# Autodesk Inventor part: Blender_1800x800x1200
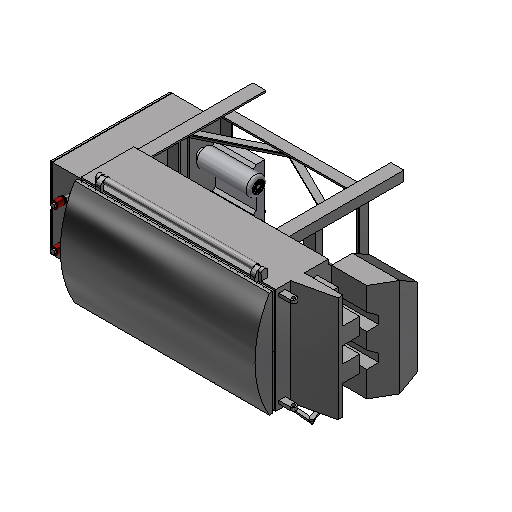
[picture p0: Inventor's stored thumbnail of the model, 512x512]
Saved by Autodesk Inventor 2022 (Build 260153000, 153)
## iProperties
Created: 2014-02
Part Number: Blender_1800x800x1200
Material: 一般
Document SubType Name: Modeling
Density: 1 g/cm^3
Appearance: 既定
Key Parameters: Width=1800.000 mm;Depth=800.000 mm;Height=1200.000 mm;
Author: Autodest, Inc.
Title: Blender
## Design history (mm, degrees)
sketch "Sketch1"
  geometry: L1 (0, -407.63)-(0, 422.253); L2 (-798, 0)-(798, 0); L3 (-473.684, 331)-(-391.866, 331); L4 (-391.866, 331)-(-391.866, 321); L5 (-463.684, 269.462)-(-473.684, 269.462); L6 (-473.684, 269.462)-(-473.684, 331); L7 (-463.684, 269.462)-(-463.684, 321); L8 (-463.684, 321)-(-391.866, 321); L9 (-473.684, -331)-(-391.866, -331); L10 (-391.866, -331)-(-391.866, -321); L11 (-463.684, -269.462)-(-473.684, -269.462); L12 (-473.684, -269.462)-(-473.684, -331); L13 (-463.684, -269.462)-(-463.684, -321); L14 (-463.684, -321)-(-391.866, -321); L15 (463.684, -269.462)-(473.684, -269.462); L16 (463.684, -321)-(391.866, -321); L17 (473.684, -331)-(391.866, -331); L18 (391.866, -331)-(391.866, -321); L19 (473.684, -269.462)-(473.684, -331); L20 (463.684, -269.462)-(463.684, -321); L21 (463.684, 269.462)-(463.684, 321); L22 (473.684, 269.462)-(473.684, 331); L23 (463.684, 321)-(391.866, 321); L24 (391.866, 331)-(391.866, 321); L25 (473.684, 331)-(391.866, 331); L26 (463.684, 269.462)-(473.684, 269.462); L27 (0, 588.23)-(0, -573.606) reference; L28 (-1117.2, 0)-(1117.2, 0) reference; 1 further point
  constraints: 52 end point, 18 symmetric about line, 3 parallel, 3 perpendicular, 2 collinear, 1 horizontal
  dimensions: "d0" = 81.81818 distance of L3.start L3.end (derived); "d1" = 61.53846 distance of L5.end L3.start (derived); "d2" = 10 distance of L3.end L4.end; "d3" = 331 distance between parallel lines of L2 L3 (derived); "d4" = 473.68421 distance between parallel lines of L1 L6 (derived)
extrude "Extrusion1" new body sketch "Sketch1" distance "d5" = 720 (derived); taper "d6" = 0 deg
sketch "Sketch2"
  geometry: L1 (0, 51.538)-(-720, 51.538) reference; L2 (0, 0)-(-720, 0) reference; L3 (0, 642)-(-720, 642) reference; L4 (-266.667, 0)-(-200, 0); L5 (-200, 51.538)-(-200, 0); L6 (-200, 642)-(-200, 590.462); L7 (-200, 642)-(-266.667, 642); L8 (-266.667, 0)-(-266.667, 642); L9 (-266.667, 0)-(-266.667, 10.308); L10 (-266.667, 0)-(-266.667, 10.308); L11 (-266.667, 10.308)-(-210.308, 10.308); L12 (-210.308, 10.308)-(-210.308, 51.538); L13 (-200, 51.538)-(-210.308, 51.538); L14 (-266.667, 642)-(-266.667, 631.692); L15 (-266.667, 631.692)-(-210.308, 631.692); L16 (-210.308, 631.692)-(-210.308, 590.462); L17 (-210.308, 590.462)-(-200, 590.462); L18 (0, 0)-(0, 51.538) reference; 1 further point
  constraints: 28 end point, 8 point on line, 6 perpendicular, 4 equal length, 3 collinear, 1 parallel, 1 vertical
  dimensions: "d9" = 66.66667 distance between parallel lines of L5 L8 (derived); "d10" = 200 distance between parallel lines of L18 L5 (= 3 x d9); "d11" = 51.53846 distance of L2.start L1.start (derived); "d12" = 10.30769 distance between parallel lines of L11 L4 (= 0.2 x d11)
extrude "Extrusion2" join sketch "Sketch2" stored distance "d7" = 720 (derived); taper "d8" = 0 deg
sketch "Sketch3"
  geometry: L1 (0, -56.359)-(927.368, -56.359) reference; L2 (463.684, 601.778)-(463.684, -437.333) reference; L3 (927.368, 0)-(927.368, 453.333) reference; L4 (463.684, -56.359)-(927.368, 170.308); L5 (927.368, 170.308)-(909.261, 207.35); L6 (909.261, 207.35)-(445.577, -19.317); L7 (445.577, -19.317)-(463.684, -56.359); 1 further point
  constraints: 8 end point, 2 parallel, 2 point on line, 1 midpoint, 1 perpendicular
  dimensions: "d13" = 226.66667 distance of L1.end L4.end (= 0.5 x d14); "d14" = 453.33333 distance of L3.start L3.end (derived); "d17" = 41.23077 distance between parallel lines of L4 L6 (= 0.8 x d11)
extrude "Extrusion3" join sketch "Sketch3" distance "d15" = 6.18462 (= 0.6 x d12); taper "d16" = 0 deg
sketch "Sketch4"
  geometry: L1 (463.684, -56.359)-(927.368, 170.308) reference; L2 (463.684, -56.359)-(927.368, 170.308); L3 (927.368, 170.308)-(922.842, 179.568); L4 (922.842, 179.568)-(459.157, -47.099); L5 (459.157, -47.099)-(463.684, -56.359); 1 further point
  constraints: 8 end point, 3 equal length, 1 perpendicular
  dimensions: "d18" = 10.30769 distance between parallel lines of L2 L4 (= d12)
extrude "Extrusion4" join sketch "Sketch4" stored distance "d19" = 5; taper "d20" = 0 deg
mirror "Mirror1"
mirror "Mirror2"
sketch "Sketch5"
  geometry: L1 (0, 1560)-(0, -260) reference; L2 (-463.4, 0)-(463.4, 0) reference; L3 (331, 0)-(331, 720) reference; L4 (-331, 0)-(-331, 720) reference; L5 (-331, 1200)-(-331, 720); L6 (331, 1200)-(331, 720); L7 (-331, 545.455)-(331, 545.455); L8 (-331, 720)-(-300.231, 720); L9 (331, 720)-(300.231, 720); L10 (-300.231, 720)-(-300.231, 1218.082); L11 (300.231, 720)-(300.231, 1223.148); L12 (-331, 1050)-(-331, 720); L13 (-331, 1200)-(331, 1200); L14 (-331, 1050)-(331, 1050); L15 (331, 1050)-(331, 720); L16 (-269.462, 436.974)-(-269.462, 720) reference; A1 r 345.482 centre (0, 890.937) between (-300.231, 720) and (300.231, 720); 1 further point
  constraints: 23 end point, 6 collinear, 6 point on line, 3 parallel, 3 perpendicular, 2 point on circle, 1 centre point, 1 tangent
  dimensions: "d23" = 1200 distance between parallel lines of L2 L13 (derived); "d24" = 150 distance from line of L13 L12.start (derived); "d123" = 545.45455 distance between parallel lines of L2 L7 (derived); "d124" = 61.53846 distance of L16.end L4.end (derived); "d125" = 30.76923 distance of L4.end L8.end (derived)
extrude "Extrusion5" new body sketch "Sketch5" distance "d25" = 720 (derived); taper "d27" = 0 deg; dims "d26" = 500 (derived), "d28" = 0
shell "Shell1" dims "d29" = 10
sketch "Sketch6"
  geometry: L1 (1220, 0)-(0, 0) reference; L2 (1220, 330)-(1220, 0) reference; L3 (0, 0)-(0, 330) reference; L4 (1130, 0)-(1110, 0); L5 (1110, 0)-(1110, 40); L6 (1110, 40)-(1130, 40); L7 (1130, 40)-(1130, 0); L8 (110, 0)-(90, 0); L9 (90, 0)-(90, 40); L10 (90, 40)-(110, 40); L11 (110, 40)-(110, 0); 1 further point
  constraints: 16 end point, 4 parallel, 2 collinear, 2 horizontal, 2 perpendicular, 2 point on line
  dimensions: "d30" = 90 distance between parallel lines of L2 L7 (derived); "d31" = 90 distance between parallel lines of L3 L9 (= d30); "d32" = 40 distance of L4.end L5.end; "d33" = 20 distance of L5.end L6.end
extrude "Extrusion6" join sketch "Sketch6" distance "d34" = 60; taper "d35" = 0 deg
sketch "Sketch7"
  geometry: L1 (40, 0)-(0, 0) reference; L2 (40, 0)-(40, 60) reference; L3 (0, 60)-(40, 60) reference; L4 (0, 0)-(0, 60) reference; L5 (0, 40)-(40, 40); A1 r 20 centre (20, 40) between (40, 40) and (0, 40); 1 further point
  constraints: 2 end point, 2 point on circle, 2 point on line, 1 centre point, 1 perpendicular, 1 tangent
  dimensions: "d36" = 40 distance of L3.start L2.end (derived); "d37" = 20 distance between parallel lines of L3 L5 (= 0.5 x d36)
extrude "Extrusion7" cut sketch "Sketch7" stored distance "d38" = 50; taper "d39" = 0 deg
workplane "Work Plane1"
  workaxis "Work Axis1"
sketch "Sketch8"
  geometry: L1 (-558.164, 1030)-(1022.249, 1030) reference; L2 (-321, 1050)-(321, 1050); L3 (321, 1050)-(321, 1070); L4 (321, 1070)-(331, 1070); L5 (-321, 1050)-(-321, 1070); L6 (-321, 1070)-(-331, 1070); L7 (-331, 1070)-(-331, 1090); L8 (331, 1070)-(331, 1090); L9 (-332.391, 1180)-(796.476, 1180); L10 (-321, 730)-(-321, 1050) reference; L11 (321, 1050)-(321, 730) reference; A1 r 653.672 centre (0, 526.328) between (331, 1090) and (-331, 1090); A2 r 20 centre (371, 1030) between (371, 1010) and (371, 1050) reference; 1 further point
  constraints: 16 end point, 4 parallel, 4 perpendicular, 2 equal length, 2 point on circle, 1 centre point, 1 collinear, 1 tangent
  dimensions: "d45" = 150 distance between parallel lines of L1 L9 (derived); "d46" = 20 distance between parallel lines of L1 L2; "d47" = 642 distance of L11.start L10.end (derived); "d48" = 642 distance of L2.start L2.end (= d47); "d50" = 20 distance between parallel lines of L2 L6; "d55" = 10 distance of L3.end L4.end; "d56" = 20 distance of L6.end L7.end; "d57" = 50 distance from line of L11 A2.centre (derived); "d58" = 50 distance from line of A2.centre L3 (= d57)
extrude "Extrusion8" new body sketch "Sketch8" distance "d41" = 720 (= d25); taper "d43" = 0 deg; dims "d42" = 500 (= d26), "d44" = 0
sketch "Sketch10"
  geometry: L1 (0, 0)-(1220, 0) reference; L2 (1220, 642)-(1220, 0) reference; L3 (1220, 642)-(0, 642) reference; L4 (0, 0)-(0, 642) reference; L5 (1210, 642)-(1210, 0); L6 (10, 642)-(10, 0); 1 further point
  constraints: 4 end point, 4 point on line, 2 perpendicular
  dimensions: "d64" = 10 distance between parallel lines of L2 L5; "d65" = 10 distance between parallel lines of L4 L6
extrude "Extrusion10" cut sketch "Sketch10" stored distance "d66" = 762.5; taper "d67" = 0 deg
shell "Shell3" dims "d68" = 5
sketch "Sketch11"
  geometry: L1 (-20, 0)-(-20, -662) reference; L2 (0, -10)-(-20, -10) reference; L3 (0, -652)-(0, -10) reference; L4 (0, -10)-(0, 18); L5 (-20, 0)-(-20, 18); L6 (-20, 18)-(0, 18); A1 r 20 centre (20, 40) between (40, 40) and (0, 40) reference; A2 r 17 centre (20, 40) between (11.881, 25.064) and (20.755, 56.983); A3 r 8.041 centre (8.041, 18) between (11.881, 25.064) and (0, 18); A4 r 39.022 centre (19.022, 18) between (20.755, 56.983) and (-20, 18); 1 further point
  constraints: 6 end point, 6 point on circle, 4 tangent, 3 centre point, 1 coincident, 1 collinear, 1 parallel, 1 perpendicular
  dimensions: "d69" = 3 radial gap between concentric circles of A1 A2; "d72" = 28 distance of L2.start L4.end
extrude "Extrusion11" join sketch "Sketch11" distance "d70" = 30; taper "d71" = 0 deg
sketch "Sketch12"
  geometry: L1 (60, -662)-(60, 0) reference; L2 (60, -10)-(40, -10) reference; L3 (40, -10)-(40, -652) reference; L4 (60, 0)-(60, 18); L5 (60, 18)-(40, 18); L6 (40, 18)-(40, -10); A1 r 20 centre (20, 40) between (40, 40) and (0, 40) reference; A2 r 17 centre (20, 40) between (28.119, 25.064) and (19.245, 56.983); A3 r 8.041 centre (31.959, 18) between (40, 18) and (28.119, 25.064); A4 r 39.022 centre (20.978, 18) between (60, 18) and (19.245, 56.983); 1 further point
  constraints: 6 end point, 6 point on circle, 4 tangent, 3 centre point, 2 parallel, 1 coincident, 1 collinear, 1 perpendicular
  dimensions: "d73" = 3 radial gap between concentric circles of A1 A2; "d74" = 28 distance of L5.end L2.end
extrude "Extrusion12" join sketch "Sketch12" distance "d75" = 30; taper "d76" = 0 deg
sketch "Sketch13"
  geometry: C1 r 20 at (20, 40); A1 r 20 centre (20, 40) between (40, 40) and (0, 40) reference; 2 further points
  constraints: 1 centre point, 1 coincident, 1 concentric
extrude "Extrusion13" join sketch "Sketch13" stored distance "d77" = 30; taper "d78" = 0 deg
sketch "Sketch14"
  geometry: L1 (71.818, -453.333)-(71.818, 0) reference; L2 (0, -453.333)-(0, 0) reference; L3 (-783.732, -720)-(-783.732, 0) reference; L4 (-891.866, 0)-(328.134, 0) reference; L5 (-865.55, -720)-(-865.55, 0) reference; L6 (0, -174.545)-(71.818, -174.545); L7 (71.818, -174.545)-(71.818, -184.545); L8 (71.818, -184.545)-(0, -184.545); L9 (0, -184.545)-(0, -174.545); L10 (71.818, -184.545)-(61.818, -184.545); L11 (61.818, -184.545)-(61.818, -220.455); L12 (61.818, -220.455)-(71.818, -220.455); L13 (71.818, -220.455)-(71.818, -184.545); L14 (-783.732, -174.545)-(-855.55, -174.545); L15 (-855.55, -174.545)-(-855.55, -184.545); L16 (-855.55, -184.545)-(-783.732, -184.545); L17 (-783.732, -184.545)-(-783.732, -174.545); L18 (-855.55, -184.545)-(-845.55, -184.545); L19 (-845.55, -184.545)-(-845.55, -220.455); L20 (-845.55, -220.455)-(-855.55, -220.455); L21 (-855.55, -220.455)-(-855.55, -184.545); L22 (-891.866, -174.545)-(328.134, -174.545) reference; 1 further point
  constraints: 32 end point, 7 parallel, 5 collinear, 4 horizontal, 4 perpendicular, 3 point on line, 2 equal length
  dimensions: "d79" = 10 distance of L8.end L6.start; "d82" = 10 distance of L11.end L12.end (derived); "d83" = 35.90909 distance between parallel lines of L12 L10 (derived); "d84" = 71.81818 distance of L7.end L8.end (derived)
extrude "Extrusion14" join sketch "Sketch14" stored distance "d80" = 30; taper "d81" = 0 deg
sketch "Sketch15"
  geometry: L1 (0, 0)-(0, 56.359) reference; L2 (0, 0)-(927.368, 0) reference; L3 (71.818, -10.308)-(855.55, -10.308) reference; L4 (927.368, 56.359)-(927.368, 289.238) reference; L5 (0, 56.359)-(8, 56.359); L6 (8, 56.359)-(8, 0); L7 (8, 0)-(0, 0); L8 (0, 0)-(0, 56.359); L9 (8, 0)-(71.818, 0); L10 (71.818, 0)-(71.818, 8); L11 (71.818, 8)-(8, 8); L12 (8, 8)-(8, 0); L13 (71.818, 56.359)-(71.818, 325.147) reference; L14 (855.55, 56.359)-(855.55, 325.147) reference; L15 (855.55, 56.359)-(927.368, 56.359) reference; L16 (927.368, 56.359)-(919.368, 56.359); L17 (919.368, 56.359)-(919.368, 0); L18 (919.368, 0)-(927.368, 0); L19 (927.368, 0)-(927.368, 56.359); L20 (927.368, 0)-(855.55, 0); L21 (855.55, 0)-(855.55, 8); L22 (855.55, 8)-(927.368, 8); L23 (927.368, 8)-(927.368, 0); 2 further points
  constraints: 32 end point, 8 parallel, 5 perpendicular, 4 collinear, 4 horizontal, 1 point on line
  dimensions: "d85" = 8 distance of L9.end L10.end; "d86" = 8 distance between parallel lines of L1 L6
extrude "Extrusion15" join sketch "Sketch15" stored distance "d88" = 30; taper "d89" = 0 deg
sketch "Sketch16"
  geometry: L1 (-56.359, 0)-(0, 0) reference; L2 (-56.359, 538.923)-(0, 538.923) reference; L3 (-56.359, 538.923)-(-56.359, 0) reference; L4 (-56.359, 157.186)-(-37.573, 157.186); L5 (-37.573, 157.186)-(-37.573, 89.821); L6 (-37.573, 89.821)-(-56.359, 89.821); L7 (-56.359, 89.821)-(-56.359, 157.186); L8 (-56.359, 381.737)-(-37.573, 381.737); L9 (-37.573, 381.737)-(-37.573, 449.103); L10 (-37.573, 449.103)-(-56.359, 449.103); L11 (-56.359, 449.103)-(-56.359, 381.737); 1 further point
  constraints: 16 end point, 4 parallel, 2 equal length, 2 horizontal, 2 perpendicular, 2 point on line
  dimensions: "d90" = 538.92308 distance of L2.start L1.start (derived); "d91" = 89.82051 distance between parallel lines of L2 L10 (derived); "d92" = 89.82051 distance between parallel lines of L1 L6 (derived); "d93" = 67.36538 distance of L8.end L9.end (derived); "d94" = 56.35897 distance of L2.start L2.end (derived); "d95" = 18.78632 distance of L9.end L10.end (derived)
extrude "Extrusion16" join sketch "Sketch16" distance "d96" = 300 (derived); taper "d97" = 0 deg
sketch "Sketch17"
  geometry: L1 (-300, 0)-(-300, 67.365) reference; L2 (-36.316, -443.276)-(-36.316, 218.724) reference; L3 (-300, 138.724)-(-51.316, 138.724); L4 (-51.316, 138.724)-(-51.316, -363.276); L5 (-51.316, -363.276)-(-300, -363.276); L6 (1183.684, -443.276)-(-36.316, -443.276) reference; L7 (-300, -102.236)-(-290, -102.236); L8 (-290, -102.236)-(-290, -122.316); L9 (-290, -122.316)-(-300, -122.316); L10 (-300, -363.276)-(-300, -122.316); L11 (-300, -102.236)-(-300, 138.724); L12 (-596.737, -112.276)-(1480.421, -112.276) reference; L13 (-290, -363.276)-(-287, -363.276); L14 (-287, -363.276)-(-287, -358.276); L15 (-287, -358.276)-(-290, -358.276); L16 (-290, -358.276)-(-290, -363.276); L17 (-290, 138.724)-(-287, 138.724); L18 (-287, 138.724)-(-287, 133.724); L19 (-287, 133.724)-(-290, 133.724); L20 (-290, 133.724)-(-290, 138.724); L21 (-10, 218.724)-(71.818, 218.724) reference; 1 further point
  constraints: 32 end point, 8 parallel, 6 collinear, 4 horizontal, 4 perpendicular, 2 point on line, 2 other
  dimensions: "d99" = 15 distance between parallel lines of L2 L4; "d100" = 80 distance between parallel lines of L6 L5; "d101" = 502 distance of L5.end L3.start (derived); "d102" = 20.08 distance of L7.end L8.end (derived); "d103" = 10 distance of L8.end L9.end; "d111" = 248.68421 distance of L3.start L3.end (derived); "d227" = 3 distance of L14.end L15.end; "d228" = 5 distance of L13.end L14.end
extrude "Extrusion17" join sketch "Sketch17" distance "d105" = 750 (derived); taper "d106" = 0 deg
sketch "Sketch18"
  geometry: L1 (-740, 720)-(-740, 480); L2 (-740, 480)-(-1036.316, 480); L3 (-1036.316, 480)-(-1036.316, 589.091); L4 (-1036.316, 589.091)-(-960.735, 720); L5 (-960.735, 720)-(-740, 720); L6 (-720, 720)-(-720, 545.455) reference; L7 (-391.866, 0)-(-463.684, 0) reference; L8 (-720, 720)-(500, 720) reference; 1 further point
  constraints: 10 end point, 2 parallel, 2 perpendicular, 1 collinear
  dimensions: "d107" = 20 distance between parallel lines of L6 L1; "d108" = 296.31579 distance of L1.end L2.end (derived); "d112" = 240 distance between parallel lines of L2 L5 (derived); "d113" = 150 deg angle of L3 L4; "d114" = 109.09091 distance of L2.end L3.end (derived)
extrude "Extrusion18" join sketch "Sketch18" stored distance "d109" = 615.38462 (derived); taper "d110" = 0 deg
sketch "Sketch19"
  geometry: L1 (0, 615.385)-(0, 0) reference; L2 (-109.091, 615.385)-(0, 615.385) reference; L3 (0, 0)-(-109.091, 0) reference; L4 (-109.091, 0)-(0, 62.984); L5 (-109.091, 615.385)-(0, 552.401); L6 (-240, 615.385)-(-240, 0) reference; L7 (-240, 160)-(-192, 187.713); L8 (-192, 187.713)-(-192, 237.713); L9 (-192, 237.713)-(-240, 265.426); L10 (-240, 365.426)-(-192, 393.138); L11 (-192, 393.138)-(-192, 443.138); L12 (-192, 443.138)-(-240, 470.851); 1 further point
  constraints: 16 end point, 6 point on line, 5 parallel, 2 collinear, 2 equal length
  dimensions: "d115" = 60 deg angle of L1 L4; "d118" = 50 distance of L7.end L8.end (derived); "d119" = 100 distance of L10.start L9.end (derived); "d120" = 48 distance between parallel lines of L6 L8 (derived); "d121" = 160 distance of L6.end L7.start (derived)
extrude "Extrusion19" cut sketch "Sketch19" stored distance "d116" = 735.5; taper "d117" = 0 deg
sketch "Sketch20"
  geometry: L1 (-720, 331)-(-1050, 331) reference; L2 (-1050, 331)-(-1050, -331) reference; L3 (-1050, -331)-(-720, -331) reference; L4 (-900, -331)-(-870, -331); L5 (-870, -331)-(-870, 331); L6 (-870, 331)-(-900, 331); L7 (-900, 331)-(-900, -331); L8 (-870, -147.692)-(-764.574, -147.692); L9 (-764.574, -147.692)-(-764.574, -42.267); L10 (-764.574, -42.267)-(-870, -42.267); L11 (-870, -42.267)-(-870, -147.692); L12 (-870, 57.733)-(-764.574, 57.733); L13 (-764.574, 57.733)-(-764.574, 163.159); L14 (-764.574, 163.159)-(-870, 163.159); L15 (-870, 163.159)-(-870, 57.733); 4 further points
  constraints: 24 end point, 6 parallel, 5 point on line, 3 equal length, 3 horizontal, 3 perpendicular, 2 collinear
  dimensions: "d126" = 30 distance between parallel lines of L5 L7; "d127" = 330 distance of L2.end L3.end (derived); "d128" = 150 distance between parallel lines of L2 L7 (derived)
extrude "Extrusion20" join sketch "Sketch20" stored distance "d129" = 735.5; taper "d130" = 0 deg
sketch "Sketch21"
  geometry: L1 (-870, -147.692)-(-870, -331) reference; L2 (-870, -331)-(-720, -331) reference; L3 (-720, -331)-(-720, -300.231) reference; L4 (-870, 331)-(-870, 163.159) reference; L5 (-870, 57.733)-(-870, -42.267) reference; L6 (-870, -42.267)-(-764.574, -42.267) reference; L7 (-870, -247.678)-(-788.182, -247.678); L8 (-788.182, -247.678)-(-788.182, -217.678); L9 (-788.182, -217.678)-(-870, -217.678); L10 (-870, -217.678)-(-870, -247.678); L11 (-870, 3.188)-(-788.182, 3.188); L12 (-788.182, 3.188)-(-788.182, 33.188); L13 (-788.182, 33.188)-(-870, 33.188); L14 (-870, 33.188)-(-870, 3.188); L15 (-870, 247.079)-(-788.182, 247.079); L16 (-788.182, 247.079)-(-788.182, 277.079); L17 (-788.182, 277.079)-(-870, 277.079); L18 (-870, 277.079)-(-870, 247.079); 1 further point
  constraints: 24 end point, 6 parallel, 4 collinear, 3 horizontal, 3 perpendicular, 2 point on line, 1 midpoint
  dimensions: "d131" = 30 distance of L7.end L8.end; "d132" = 68.18182 distance between parallel lines of L3 L8 (derived); "d133" = 150 distance of L1.end L2.end (derived); "d134" = 183.30769 distance of L1.start L1.end (derived); "d135" = 83.32168 distance between parallel lines of L2 L7 (derived); "d136" = 100 distance of L5.start L5.end (derived); "d137" = 45.45455 distance between parallel lines of L6 L11 (derived)
extrude "Extrusion21" join sketch "Sketch21" distance "d138" = 128.57143 (derived); taper "d139" = 0 deg
sketch "Sketch22"
  geometry: L1 (0, 81.818)-(128.571, 0); C1 r 12.5 at (64.286, 40.909); 2 further points
  constraints: 2 end point, 1 centre point, 1 coincident, 1 midpoint
  dimensions: "d141" = 25 diameter of C1
extrude "Extrusion22" join sketch "Sketch22" stored distance "d142" = 756.5; taper "d143" = 0 deg
sketch "Sketch23"
  geometry: C1 r 12.5 at (0, 0) reference; C2 r 9.5 at (0, 0); 1 further point
  constraints: 1 centre point, 1 coincident
  dimensions: "d144" = 3 radial gap between concentric circles of C1 C2
extrude "Extrusion23" join sketch "Sketch23" distance "d145" = 50; taper "d146" = 0 deg
sketch "Sketch24"
  geometry: L1 (0, 0)-(34.202, 93.969); L2 (-11.746, 4.275)-(22.456, 98.245); L3 (45.948, 89.694)-(11.746, -4.275); L4 (-64.286, 70.909)-(176.45, 70.909) reference; C1 r 9.5 at (0, 0) reference; C2 r 12.5 at (0, 0) reference; A1 r 12.5 centre (0, 0) between (-11.746, 4.275) and (11.746, -4.275); A2 r 12.5 centre (34.202, 93.969) between (45.948, 89.694) and (22.456, 98.245); 3 further points
  constraints: 8 end point, 4 point on circle, 4 tangent, 2 centre point, 1 coincident, 1 concentric, 1 midpoint, 1 parallel
  dimensions: "d150" = 70 deg angle of L4 L3; "d151" = 100 distance of point (0, 0) L1.end
extrude "Extrusion24" join sketch "Sketch24" distance "d148" = 10; taper "d149" = 0 deg
sketch "Sketch25"
  geometry: L1 (22.456, 98.245)-(-11.746, 4.275) reference; L2 (34.202, 93.969)-(-115.227, 80.896); L3 (35.204, 82.513)-(-114.225, 69.44); L4 (-116.229, 92.352)-(33.2, 105.426); A1 r 12.5 centre (34.202, 93.969) between (45.948, 89.694) and (22.456, 98.245) reference; A2 r 11.5 centre (34.202, 93.969) between (35.204, 82.513) and (33.2, 105.426); A3 r 11.5 centre (-115.227, 80.896) between (-116.229, 92.352) and (-114.225, 69.44); 2 further points
  constraints: 8 end point, 4 point on circle, 4 tangent, 2 centre point, 1 midpoint, 1 parallel
  dimensions: "d152" = 1 radial gap between concentric circles of A1 A2; "d153" = 65 deg angle of L1 L3; "d154" = 150 distance of L2.start L2.end
extrude "Extrusion25" join sketch "Sketch25" distance "d155" = 10; taper "d156" = 0 deg
sketch "Sketch26"
  geometry: L1 (16.122, -80.844)-(-114.225, -69.44) reference; L2 (-115.227, -80.896)-(-170.168, 36.924); L3 (-102.992, -75.191)-(-157.932, 42.629); L4 (-182.403, 31.219)-(-127.462, -86.601); A1 r 11.5 centre (-115.227, -80.896) between (-114.225, -69.44) and (-116.229, -92.352) reference; A2 r 13.5 centre (-115.227, -80.896) between (-127.462, -86.601) and (-102.992, -75.191); A3 r 13.5 centre (-170.168, 36.924) between (-157.932, 42.629) and (-182.403, 31.219); 2 further points
  constraints: 8 end point, 4 point on circle, 4 tangent, 2 centre point, 1 midpoint, 1 parallel
  dimensions: "d157" = 2 radial gap between concentric circles of A2 A1; "d158" = 130 distance of L2.start L2.end; "d159" = 120 deg angle of L3 L1
extrude "Extrusion26" join sketch "Sketch26" distance "d160" = 10; taper "d161" = 0 deg
sketch "Sketch27"
  geometry: L1 (-183.668, 50.424)-(-157.932, 50.424); L2 (-157.932, 50.424)-(-157.932, 24.689); L3 (-157.932, 24.689)-(-183.668, 24.689); L4 (-183.668, 24.689)-(-183.668, 50.424); A1 r 13.5 centre (-170.168, 36.924) between (-157.932, 42.629) and (-182.403, 31.219) reference; 1 further point
  constraints: 8 end point, 2 parallel, 2 perpendicular, 2 tangent, 1 horizontal, 1 point on line
extrude "Extrusion27" join sketch "Sketch27" stored distance "d162" = 10; taper "d163" = 0 deg
sketch "Sketch28"
  geometry: L1 (-110.405, 87.279)-(-107.288, 79.911); L2 (-107.288, 79.911)-(-112.111, 73.528); L3 (-112.111, 73.528)-(-120.05, 74.513); L4 (-120.05, 74.513)-(-123.166, 81.881); L5 (-123.166, 81.881)-(-118.344, 88.264); L6 (-118.344, 88.264)-(-110.405, 87.279); L7 (27.431, 98.23)-(34.507, 101.963); L8 (34.507, 101.963)-(41.278, 97.702); L9 (41.278, 97.702)-(40.973, 89.708); L10 (40.973, 89.708)-(33.897, 85.975); L11 (33.897, 85.975)-(27.126, 90.236); L12 (27.126, 90.236)-(27.431, 98.23); A1 r 11.5 centre (34.202, 93.969) between (35.204, 82.513) and (33.2, 105.426) reference; A2 r 11.5 centre (-115.227, 80.896) between (-116.229, 92.352) and (-114.225, 69.44) reference; 3 further points
  constraints: 24 end point, 2 coincident, 1 equal length, 26 other
  dimensions: "d164" = 8 distance of L7.end L8.end
extrude "Extrusion28" join sketch "Sketch28" distance "d165" = 8; taper "d166" = 0 deg
sketch "Sketch29"
  geometry: L1 (600, 185)-(675, 185); L2 (675, 185)-(675, 110); L3 (675, 110)-(600, 110); L4 (600, 110)-(600, 185); L5 (1220, 0)-(0, 0) reference; L6 (0, 0)-(0, 330) reference; 1 further point
  constraints: 8 end point, 2 parallel, 2 perpendicular, 1 horizontal
  dimensions: "d179" = 330 distance of L5.end L6.end (derived); "d180" = 110 distance between parallel lines of L5 L3 (derived); "d181" = 600 distance between parallel lines of L6 L4 (derived); "d182" = 75 distance of L1.end L2.end
extrude "Extrusion29" join sketch "Sketch29" distance "d167" = 8; taper "d168" = 0 deg
sketch "Sketch30"
  geometry: L1 (-179.358, 24.689)-(-127.462, -86.601) reference; L2 (-115.227, -80.896)-(-180.759, -126.782); L3 (-122.97, -69.837)-(-188.503, -115.723); L4 (-173.016, -137.841)-(-107.484, -91.954); A1 r 13.5 centre (-115.227, -80.896) between (-127.462, -86.601) and (-102.992, -75.191) reference; A2 r 13.5 centre (-115.227, -80.896) between (-107.484, -91.954) and (-122.97, -69.837); A3 r 13.5 centre (-180.759, -126.782) between (-188.503, -115.723) and (-173.016, -137.841); 2 further points
  constraints: 8 end point, 4 point on circle, 4 tangent, 2 centre point, 1 concentric, 1 midpoint, 1 parallel
  dimensions: "d169" = 100 deg angle of L1 L3; "d170" = 80 distance of L2.start L2.end
extrude "Extrusion30" join sketch "Sketch30" distance "d171" = 8; taper "d172" = 0 deg
sketch "Sketch31"
  geometry: L1 (675, 185)-(600, 185) reference; L2 (600, 185)-(600, 110) reference; L3 (600, 110)-(675, 110) reference; L4 (675, 110)-(675, 185) reference; L5 (610, 175)-(665, 175); L6 (665, 175)-(665, 120); L7 (665, 120)-(610, 120); L8 (610, 120)-(610, 175); 1 further point
  constraints: 8 end point, 3 other
  dimensions: "d173" = 10 distance between parallel lines of L4 L6
extrude "Extrusion31" join sketch "Sketch31" distance "d174" = 38; taper "d175" = 0 deg
sketch "Sketch32"
  geometry: L1 (610, 175)-(610, 120) reference; L2 (1111.27, 246.931)-(1176.802, 201.045) reference; L3 (1152.036, 185.426)-(1095.783, 224.814) reference; L4 (1152.036, 185.426)-(1156.823, 195.692) reference; L5 (610, 175)-(665, 120); L6 (665, 175)-(610, 120); L7 (637.5, 147.5)-(1103.526, 235.873); L8 (637.5, 147.5)-(1103.526, 235.873); L9 (1103.526, 235.873)-(1101.663, 245.698); L10 (1101.663, 245.698)-(635.637, 157.325); L11 (635.637, 157.325)-(637.5, 147.5); L12 (879.046, 203.483)-(876.252, 218.22); L13 (876.252, 218.22)-(664.421, 178.051); L14 (1101.663, 245.698)-(1103.526, 235.873); L15 (1103.526, 235.873)-(1112.472, 237.569); L16 (1112.472, 237.569)-(1110.609, 247.394); L17 (1110.609, 247.394)-(1101.663, 245.698); L18 (637.5, 147.5)-(635.637, 157.325); L19 (635.637, 157.325)-(610, 152.463); L20 (610, 152.463)-(611.863, 142.638); L21 (611.863, 142.638)-(637.5, 147.5); L22 (664.421, 178.051)-(667.216, 163.313); A1 r 13.5 centre (1169.059, 189.987) between (1176.802, 201.045) and (1156.823, 195.692) reference; A2 r 13.5 centre (1103.526, 235.873) between (1111.27, 246.931) and (1095.783, 224.814) reference; 1 further point
  constraints: 36 end point, 7 equal length, 6 perpendicular, 6 point on line, 1 midpoint
  dimensions: "d183" = 10 distance between parallel lines of L8 L10; "d184" = 15 distance between parallel lines of L10 L13; "d185" = 474.33147 distance of L9.end L10.end (derived); "d275" = 215.60521 distance of L12.end L13.end (derived)
revolve "Revolution1" sketch "Sketch32" stored, may be unused: angle "d176" = 90 deg
sketch "Sketch33"
  geometry: L1 (-51.316, 138.724)-(-300, 138.724) reference; L2 (-300, -363.276)-(-51.316, -363.276) reference; L3 (-51.316, 138.724)-(-300, -363.276); L4 (-300, 138.724)-(-51.316, -363.276); L5 (-175.658, -112.276)-(-175.658, 138.724); L6 (-175.658, -112.276)-(-175.658, -363.276); C1 r 10 at (-175.658, 13.224); C2 r 10 at (-175.658, -237.776); 1 further point
  constraints: 8 end point, 5 midpoint, 2 centre point, 1 equal radius
  dimensions: "d187" = 251 distance of L5.start L5.end (derived); "d188" = 125.5 distance from line of L1 C1.centre (derived); "d189" = 125.5 distance from line of L2 C2.centre (derived); "d190" = 20 diameter of C1
extrude "Extrusion32" join sketch "Sketch33" distance "d191" = 40; taper "d192" = 0 deg
sketch "Sketch34"
  geometry: C1 r 10 at (0, 0) reference; C2 r 20 at (0, 0); 1 further point
  constraints: 1 centre point
  dimensions: "d193" = 10 radial gap between concentric circles of C1 C2
extrude "Extrusion33" join sketch "Sketch34" distance "d194" = 15; taper "d195" = 0 deg
sketch "Sketch35"
  geometry: C1 r 20 at (0, 0) reference; C2 r 23 at (0, 0); 1 further point
  constraints: 1 centre point
  dimensions: "d196" = 3 radial gap between concentric circles of C2 C1
extrude "Extrusion34" join sketch "Sketch35" distance "d197" = 45; taper "d198" = 0 deg
sketch "Sketch36"
  geometry: L1 (712.427, 259.422)-(712.427, 18.462) reference; L2 (-37.573, 259.422)-(712.427, 259.422) reference; L3 (472.427, 227.422)-(312.427, 227.422); L4 (312.427, 227.422)-(312.427, 127.422); L5 (312.427, 127.422)-(472.427, 127.422); L6 (472.427, 127.422)-(472.427, 227.422); 1 further point
  constraints: 8 end point, 2 parallel, 1 horizontal, 1 perpendicular
  dimensions: "d199" = 240 distance between parallel lines of L1 L6 (derived); "d200" = 160 distance of L4.end L5.end (derived); "d201" = 32 distance between parallel lines of L2 L3 (derived); "d202" = 100 distance of L3.end L4.end (derived)
extrude "Extrusion35" cut sketch "Sketch36" distance "d203" = 2; taper "d204" = 0 deg
sketch "Sketch37"
  geometry: L1 (312.427, 227.422)-(472.427, 227.422) reference; L2 (419.094, 214.922)-(379.094, 214.922); L3 (379.094, 214.922)-(379.094, 194.922); L4 (379.094, 194.922)-(419.094, 194.922); L5 (419.094, 194.922)-(419.094, 214.922); L6 (381.094, 212.922)-(417.094, 212.922); L7 (417.094, 212.922)-(417.094, 196.922); L8 (417.094, 196.922)-(381.094, 196.922); L9 (381.094, 196.922)-(381.094, 212.922); 3 further points; 1 other entity
  constraints: 16 end point, 4 parallel, 2 perpendicular, 1 horizontal, 4 other
  dimensions: "d205" = 160 distance of L1.start L1.end (derived); "d206" = 53.33333 dimension on L5 (derived); "d207" = 40 distance of L3.end L4.end (derived); "d208" = 100 distance of L1.end point (472.427, 127.422) (derived); "d209" = 12.5 distance between parallel lines of L1 L2 (derived); "d210" = 20 distance of L2.end L3.end (derived); "d213" = 2 distance between parallel lines of L6 L2
extrude "Extrusion36" cut sketch "Sketch37" distance "d211" = 15; taper "d212" = 0 deg
sketch "Sketch38"
  geometry: C1 r 23 at (0, 0) reference; C2 r 13 at (0, 0); 1 further point
  constraints: 1 centre point
  dimensions: "d214" = 10 radial gap between concentric circles of C1 C2
extrude "Extrusion37" join sketch "Sketch38" distance "d215" = 10; taper "d216" = 0 deg
mirror "Mirror3"
sketch "Sketch39"
  geometry: L1 (-900, 331)-(-1050, 331) reference; L2 (-1050, 331)-(-1050, -331) reference; L3 (-1050, -331)-(-900, -331) reference; L4 (-1030, -301)-(-990, -301); L5 (-990, -301)-(-990, -281); L6 (-990, -281)-(-1030, -281); L7 (-1030, -281)-(-1030, -301); L8 (-1030, 281)-(-990, 281); L9 (-990, 281)-(-990, 301); L10 (-990, 301)-(-1030, 301); L11 (-1030, 301)-(-1030, 281); 1 further point
  constraints: 16 end point, 4 parallel, 2 equal length, 2 horizontal, 2 perpendicular, 1 collinear
  dimensions: "d217" = 30 distance between parallel lines of L3 L4; "d218" = 30 distance between parallel lines of L1 L10 (derived); "d219" = 20 distance between parallel lines of L2 L7; "d220" = 20 distance of L4.end L5.end; "d221" = 40 distance of L4.start L4.end (derived)
extrude "Extrusion38" join sketch "Sketch39" distance "d222" = 90 (derived); taper "d223" = 0 deg
sketch "Sketch40"
  geometry: L1 (0, 0)-(0, 40) reference; L2 (0, 0)-(90, 0) reference; L3 (90, 40)-(90, 0) reference; L4 (0, 40)-(90, 40) reference; C1 r 10 at (70, 20); A1 r 20 centre (70, 20) between (70, 0) and (70, 40); A2 r 20 centre (70, 20) between (70, 0) and (70, 40); 1 further point
  constraints: 4 point on circle, 4 tangent, 3 centre point, 2 point on line, 1 coincident
  dimensions: "d224" = 10 radial gap between concentric circles of A2 C1
extrude "Extrusion39" cut sketch "Sketch40" stored distance "d225" = 72 (derived); taper "d226" = 0 deg
sketch "Sketch41"
  geometry: L1 (-290, 133.724)-(-287, 133.724); L2 (-287, 133.724)-(-287, -358.276); L3 (-287, -358.276)-(-290, -358.276); L4 (-290, -358.276)-(-290, 133.724); 1 further point
  constraints: 8 end point, 2 parallel, 1 horizontal, 1 perpendicular
extrude "Extrusion40" cut sketch "Sketch41" distance "d229" = 5; taper "d230" = 0 deg
sketch "Sketch42"
  geometry: L1 (-150, -621.385)-(0, -621.385); L2 (0, -621.385)-(0, 0); L3 (0, 0)-(-150, 0); L4 (-150, 0)-(-150, -621.385); L5 (48.359, -621.385)-(0, -621.385) reference; 1 further point
  constraints: 8 end point, 2 parallel, 1 collinear, 1 horizontal, 1 perpendicular
  dimensions: "d316" = 150 distance of L1.start L1.end (derived)
extrude "Extrusion41" join sketch "Sketch42" stored distance "d231" = 5; taper "d232" = 0 deg
sketch "Sketch43"
  geometry: L1 (-198.359, 621.385)-(-198.359, 0) reference; L2 (-198.359, 0)-(-48.359, 0) reference; C1 r 32.5 at (-123.359, 186.415); C2 r 32.5 at (-123.359, 434.969)
  constraints: 2 centre point, 1 equal radius
  dimensions: "d317" = 150 distance of L1.end L2.end (derived); "d318" = 75 distance from line of L1 C1.centre (derived); "d319" = 621.38462 distance of L1.start L1.end (derived); "d320" = 248.55385 distance of C2.centre C1.centre (derived); "d321" = 186.41538 distance from line of L2 C1.centre (derived); "d322" = 75 distance from line of L1 C2.centre (derived); "d323" = 65 diameter of C2
extrude "Extrusion42" new body sketch "Sketch43" distance "d233" = 30; taper "d234" = 0 deg
sketch "Sketch44"
  geometry: L1 (57.5, -57.5)-(111.359, -57.5); L2 (111.359, -57.5)-(111.359, 306.054); L3 (111.359, 306.054)-(57.5, 306.054); L4 (57.5, 306.054)-(57.5, -57.5); L5 (0, 0)-(57.5, -57.5); L6 (0, 248.554)-(57.5, 306.054); L7 (0, 248.554)-(57.5, 191.054); L8 (0, 0)-(57.5, 57.5); L9 (123.359, -186.415)-(123.359, 434.969) reference; C1 r 32.5 at (0, 0) reference; C2 r 32.5 at (0, 248.554) reference; C3 r 57.5 at (0, 0); C4 r 57.5 at (0, 248.554); 1 further point
  constraints: 16 end point, 5 perpendicular, 2 centre point, 2 coincident, 2 parallel, 2 point on line, 1 equal radius, 1 horizontal, 1 tangent
  dimensions: "d240" = 25 radial gap between concentric circles of C1 C3; "d241" = 12 distance between parallel lines of L9 L2 (derived)
extrude "Extrusion43" join sketch "Sketch44" distance "d236" = 257.14286 (derived); taper "d237" = 0 deg
sketch "Sketch45"
  geometry: C1 r 57.5 at (0, 0); A1 r 57.5 centre (0, 248.554) between (40.659, 289.212) and (40.659, 207.895) reference; A2 r 57.5 centre (0, 0) between (40.659, 40.659) and (40.659, -40.659) reference; 2 further points
  constraints: 2 coincident, 1 centre point, 1 concentric, 3 other
extrude "Extrusion44" join sketch "Sketch45" distance "d242" = 72 (derived); taper "d243" = 0 deg
fillet "Fillet1" dims "d244" = 20
sketch "Sketch46" dims "d262" = 5, "d264" = 5 (derived), "d265" = 5 (derived), "d267" = 5 (derived), "d268" = 5 (derived), "d269" = 10 deg, "d271" = 10 deg (derived), "d273" = 60 deg (derived)
  geometry: L1 (-25.909, 275.664)-(-22.455, 272.049); L2 (-19, 268.435)-(-15.546, 264.82); L3 (-12.091, 261.205)-(-8.636, 257.591); L4 (-30.223, 270.753)-(-26.193, 267.793); L5 (-22.164, 264.833)-(-18.134, 261.873); L6 (-14.104, 258.914)-(-10.074, 255.954); L7 (-36.433, 239.671)-(-31.575, 240.855); L8 (-26.717, 242.04)-(-21.86, 243.224); L9 (-17.002, 244.409)-(-12.144, 245.593); L10 (-34.337, 233.479)-(-29.759, 235.489); L11 (-25.18, 237.499)-(-20.602, 239.509); L12 (-6.314, 226.958)-(-7.717, 222.159); L13 (-9.12, 217.36)-(-10.524, 212.561); L14 (0, 216.054)-(0, 211.054); L15 (0, 226.054)-(0, 221.054); L16 (0, 236.054)-(0, 231.054); L17 (15.546, 232.288)-(19, 228.673); L18 (22.455, 225.058)-(25.909, 221.444); L19 (10.074, 241.154)-(14.104, 238.194); L20 (18.134, 235.234)-(22.164, 232.274); L21 (26.193, 229.314)-(30.223, 226.355); L22 (12.144, 251.515)-(17.002, 252.699); L23 (21.86, 253.884)-(26.717, 255.068); L24 (31.575, 256.252)-(36.433, 257.437); L25 (11.446, 253.579)-(16.024, 255.589); L26 (29.759, 261.618)-(34.337, 263.628); L27 (3.508, 260.552)-(4.911, 265.351); L28 (10.524, 284.547)-(9.12, 279.748); L29 (3.017, 275.888)-(2.468, 270.918); L30 (1.92, 265.948)-(1.371, 260.978); L31 (10.524, 284.547)-(9.12, 279.748); L32 (4.911, 265.351)-(3.508, 260.552); L33 (8.636, 239.517)-(12.091, 235.902); L34 (20.602, 257.598)-(25.18, 259.608); L35 (7.717, 274.949)-(6.314, 270.15); L36 (4.114, 285.828)-(3.565, 280.858); L37 (-3.508, 236.556)-(-4.911, 231.757); L38 (-16.024, 241.519)-(-11.446, 243.529); A1 r 32.5 centre (0, 248.554) between (3.565, 280.858) and (-22.455, 272.049); A2 r 32.5 centre (0, 248.554) between (-26.193, 267.793) and (-31.575, 240.855); A3 r 32.5 centre (0, 248.554) between (-29.759, 235.489) and (-9.12, 217.36); A4 r 27.5 centre (0, 248.554) between (-25.18, 237.499) and (-7.717, 222.159); A5 r 22.5 centre (0, 248.554) between (-20.602, 239.509) and (-6.314, 226.958); A6 r 17.5 centre (0, 248.554) between (-16.024, 241.519) and (-4.911, 231.757); A7 r 12.5 centre (0, 248.554) between (-11.446, 243.529) and (-3.508, 236.556); A8 r 12.5 centre (0, 248.554) between (0, 236.054) and (8.636, 239.517); A9 r 17.5 centre (0, 248.554) between (0, 231.054) and (12.091, 235.902); A10 r 22.5 centre (0, 248.554) between (0, 226.054) and (15.546, 232.288); A11 r 27.5 centre (0, 248.554) between (0, 221.054) and (19, 228.673); A12 r 32.5 centre (0, 248.554) between (0, 216.054) and (22.455, 225.058); A13 r 27.5 centre (0, 248.554) between (-22.164, 264.833) and (-26.717, 242.04); A14 r 22.5 centre (0, 248.554) between (-18.134, 261.873) and (-21.86, 243.224); A15 r 17.5 centre (0, 248.554) between (-14.104, 258.914) and (-17.002, 244.409); A16 r 12.5 centre (0, 248.554) between (-10.074, 255.954) and (-12.144, 245.593); A17 r 27.5 centre (0, 248.554) between (3.017, 275.888) and (-19, 268.435); A18 r 22.5 centre (0, 248.554) between (2.468, 270.918) and (-15.546, 264.82); A19 r 17.5 centre (0, 248.554) between (1.92, 265.948) and (-12.091, 261.205); A20 r 12.5 centre (0, 248.554) between (1.371, 260.978) and (-8.636, 257.591); A21 r 12.5 centre (0, 248.554) between (11.446, 253.579) and (3.508, 260.552); A22 r 17.5 centre (0, 248.554) between (16.024, 255.589) and (4.911, 265.351); A23 r 22.5 centre (0, 248.554) between (20.602, 257.598) and (6.314, 270.15); A24 r 27.5 centre (0, 248.554) between (25.18, 259.608) and (7.717, 274.949); A25 r 32.5 centre (0, 248.554) between (29.759, 261.618) and (9.12, 279.748); A26 r 12.5 centre (0, 248.554) between (10.074, 241.154) and (12.144, 251.515); A27 r 17.5 centre (0, 248.554) between (14.104, 238.194) and (17.002, 252.699); A28 r 22.5 centre (0, 248.554) between (18.134, 235.234) and (21.86, 253.884); A29 r 27.5 centre (0, 248.554) between (22.164, 232.274) and (26.717, 255.068); A30 r 32.5 centre (0, 248.554) between (26.193, 229.314) and (31.575, 256.252); 13 further points
  constraints: 76 end point, 60 point on circle, 30 centre point, 16 collinear, 5 coincident, 2 point on line, 1 vertical, 202 other
extrude "Extrusion45" cut sketch "Sketch46" distance "d250" = 2; taper "d251" = 0 deg
mirror "Mirror4"
sketch "Sketch47"
  geometry: L1 (-572.22, -133.333)-(-632.22, -133.333); L2 (-632.22, -133.333)-(-632.22, 133.333); L3 (-632.22, 133.333)-(-572.22, 133.333); L4 (-572.22, 133.333)-(-572.22, -133.333); A1 r 345.482 centre (-890.937, 0) between (-720, -300.231) and (-720, 300.231) reference; 1 further point
  constraints: 8 end point, 2 parallel, 2 point on circle, 1 horizontal, 1 perpendicular
  dimensions: "d276" = 266.66667 distance of L3.end L1.start (derived); "d277" = 60 distance of L2.end L3.end (derived)
extrude "Extrusion46" join sketch "Sketch47" stored distance "d278" = 2; taper "d279" = 0 deg
sketch "Sketch48"
  geometry: L1 (1220, 180)-(1460.735, 180) reference; L2 (1220, 330)-(1220, 180) reference; L3 (1460.735, 180)-(1220, 235); L4 (1220, 270)-(1290, 270) reference; 1 further point
  constraints: 2 end point, 1 point on line
  dimensions: "d280" = 35 distance from line of L4 L3.end
extrude "Extrusion47" join sketch "Sketch48" stored distance "d281" = 2; taper "d282" = 0 deg
sketch "Sketch49"
  geometry: L1 (665, 120)-(610, 120) reference; L2 (610, 175)-(665, 120); C1 r 14.427 at (637.5, 147.5); 1 further point
  constraints: 2 end point, 1 centre point, 1 midpoint
extrude "Extrusion48" join sketch "Sketch49" distance "d283" = 12.5; taper "d284" = 0 deg
sketch "Sketch50"
  geometry: C1 r 5.081 at (-180.759, 126.782); A1 r 13.5 centre (-180.759, 126.782) between (-173.016, 137.841) and (-192.205, 133.94) reference; 1 further point
  constraints: 1 centre point, 1 coincident
extrude "Extrusion49" join sketch "Sketch50" distance "d285" = 12.5; taper "d286" = 0 deg
sketch "Sketch51"
  geometry: L1 (-159.063, -321)-(-159.063, 321) reference; L2 (-159.063, -17.5)-(-147.063, -17.5); L3 (-147.063, -17.5)-(-147.063, 17.5); L4 (-147.063, 17.5)-(-159.063, 17.5); L5 (-159.063, 17.5)-(-159.063, -17.5); L6 (-159.063, -10)-(-153.063, -10); L7 (-153.063, -10)-(-153.063, 10); L8 (-153.063, 10)-(-159.063, 10); L9 (-159.063, 10)-(-159.063, -10); L10 (-159.063, 321)-(160.937, 321) reference; L11 (-441.198, 0)-(1151.302, 0) reference; L12 (335.482, 0)-(335.482, 321); L13 (335.482, 321)-(160.937, 321); C1 r 30 at (88.209, 0); A1 r 335.482 centre (0, 0) between (160.937, -294.36) and (160.937, 294.36) reference; 1 further point
  constraints: 20 end point, 4 parallel, 3 perpendicular, 3 point on line, 2 horizontal, 1 centre point, 1 collinear, 1 point on circle, 1 tangent, 2 other
  dimensions: "d290" = 12 distance of L3.end L4.end; "d291" = 6 distance of L7.end L8.end; "d292" = 35 distance of L2.end L3.end; "d293" = 20 distance of L6.end L7.end; "d312" = 494.54545 distance between parallel lines of L1 L12 (derived); "d313" = 247.27273 distance from line of L12 C1.centre (derived); "d314" = 60 diameter of C1
extrude "Extrusion50" new body sketch "Sketch51" stored distance "d288" = 12.5; taper "d289" = 0 deg
sketch "Sketch52"
  geometry: L1 (10.007, 830.51)-(-102.062, 870.876); L2 (-115.472, 844.287)-(-16.392, 778.165); C1 r 30 at (0, 802.727) reference; A1 r 29.53 centre (0, 802.727) between (10.007, 830.51) and (-16.392, 778.165); A2 r 15 centre (-107.145, 856.764) between (-102.062, 870.876) and (-115.472, 844.287); 1 further point
  constraints: 4 end point, 4 point on circle, 4 tangent, 2 centre point, 1 concentric
  dimensions: "d295" = 30 diameter of A2; "d315" = 120 distance of A2.centre A1.centre
extrude "Extrusion51" join sketch "Sketch52" stored distance "d296" = 15; taper "d297" = 0 deg
pattern_circular "Circular Pattern1" dims angle "d299" = 360 deg
pattern_linear "Rectangular Pattern1" dims "d303" = 180 (derived)
sketch "Sketch53"
  geometry: L1 (0, 0)-(0, 25) reference; L2 (1190, 0)-(0, 0) reference; L3 (0, 25)-(1190, 25) reference; L4 (99.167, 0)-(134.167, 0); L5 (134.167, 0)-(134.167, 25); L6 (134.167, 25)-(99.167, 25); L7 (99.167, 25)-(99.167, 0); L8 (99.167, 12.5)-(134.167, 12.5); 1 further point
  constraints: 10 end point, 2 midpoint, 2 parallel, 2 point on line, 1 horizontal, 1 perpendicular
  dimensions: "d304" = 1190 distance of L1.end L3.end (derived); "d305" = 35 distance of L4.start L4.end; "d306" = 99.16667 distance between parallel lines of L1 L7 (derived)
extrude "Extrusion52" join sketch "Sketch53" stored distance "d307" = 15; taper "d308" = 0 deg
pattern_linear "Rectangular Pattern2" dims "d311" = 198.33333 (derived)
node "Landing Surface"
node "Insertion Point1"
body "Solid1"
body "Solid2"
body "Solid3"
node "Projected Loop2"
body "Solid4"
body "Solid5"
other parameters: "d40" = 0 (computed from Angle), "Angle" = 0 [user parameter; used in 1 equation term], "d246" = 60 deg, "d247" = 60 deg (derived), "d253" = 5, "d254" = 5 (derived), "d255" = 5 (derived), "d256" = 5 (derived), "d270" = 10 deg (derived), "d272" = 60 deg
